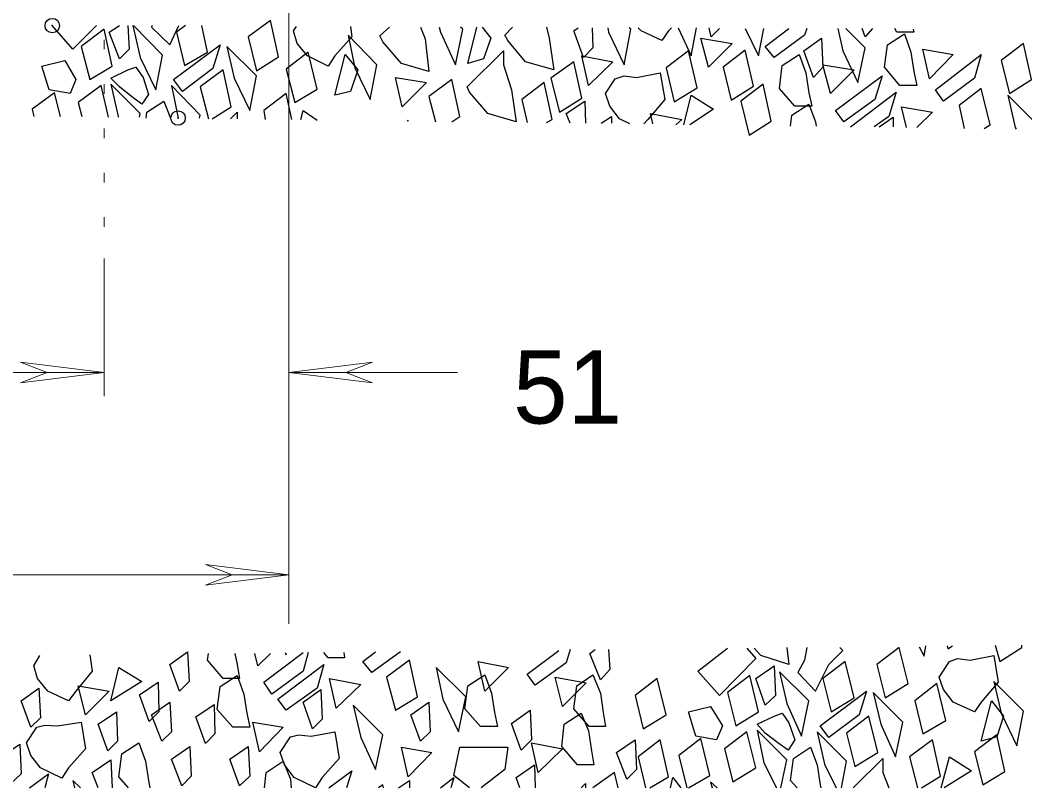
# Model space of a CAD drawing. Extents: x 312583 to 312854, y 144419 to 144597.
# Drawn here: x 312660.36 to 312670.78, y 144443.12 to 144451.08 of the extents above; entities that cross this region are included whole.
import ezdxf

# ---------------------------------------------------------------- set-up
doc = ezdxf.new("R2010")
doc.units = 0
doc.header["$LTSCALE"] = 0.3
doc.header["$PDMODE"] = 32
doc.header["$PDSIZE"] = 0.15
doc.linetypes.add('DOTTED', pattern=[1.5, 0.3, -1.2])
doc.layers.add('1', color=7, linetype='Continuous', lineweight=25)
doc.layers.add('2', color=7, linetype='Continuous', lineweight=13)

msp = doc.modelspace()

# ---------------------------------------------------------------- linework, layer by layer
at = {"layer": '1'}
for p, q in [((312661.8381, 144450.7184), (312661.5391, 144451.0251)), ((312661.9148, 144450.8258), (312662.0068, 144451.0251)), ((312662.3058, 144450.7491), (312662.2445, 144451.0251)), ((312664.9508, 144450.9868), (312664.9278, 144451.0098)), ((312665.1501, 144451.0098), (312665.2421, 144450.8948)), ((312666.6911, 144450.9868), (312666.6758, 144451.0021)), ((312667.1128, 144451.0021), (312667.0821, 144450.9714)), ((312668.5158, 144450.9944), (312668.4928, 144450.9254)), ((312669.1215, 144450.7951), (312668.9221, 144450.9944)), ((312661.8535, 144450.2431), (312661.9225, 144450.0668)), ((312666.2158, 144450.2431), (312666.2235, 144450.0131)), ((312661.6005, 144450.0744), (312661.6081, 144450.1128)), ((312662.3518, 144450.0591), (312662.5511, 144450.1818)), ((312667.5498, 144450.1588), (312667.3045, 144449.9978)), ((312669.8191, 144450.1281), (312669.6581, 144449.9671)), ((312662.2215, 144450.0668), (312662.2291, 144450.0974)), ((312664.8358, 144450.0284), (312664.9201, 144450.0821)), ((312665.8171, 144450.0208), (312665.8785, 144450.0514)), ((312666.3845, 144450.0131), (312666.4918, 144450.0821)), ((312666.4918, 144450.0821), (312666.4918, 144450.0131)), ((312666.8675, 144450.0514), (312666.8291, 144450.0054)), ((312667.2201, 144450.0514), (312667.1588, 144449.9978)), ((312669.3668, 144450.0821), (312669.2135, 144449.9748)), ((312669.2671, 144449.9748), (312669.4128, 144450.0744)), ((312669.4128, 144450.0744), (312669.4128, 144449.9748)), ((312670.3558, 144449.9594), (312670.4171, 144449.9978)), ((312670.7468, 144444.5774), (312670.7468, 144444.6004)), ((312663.3485, 144444.5238), (312663.2948, 144444.3321)), ((312666.0625, 144444.5544), (312666.0241, 144444.4164)), ((312661.3015, 144443.4121), (312661.3168, 144443.1208)), ((312665.6945, 144443.3584), (312665.7021, 144443.1208)), ((312668.2475, 144443.1208), (312668.3088, 144443.4121)), ((312668.8761, 144443.1208), (312668.9298, 144443.3968)), ((312665.3878, 144443.3124), (312665.1425, 144443.1208)), ((312667.2891, 144443.1208), (312667.5115, 144443.2511)), ((312669.3055, 144443.2818), (312669.3668, 144443.1208)), ((312669.7041, 144443.1208), (312669.9035, 144443.2434)), ((312670.2255, 144443.2971), (312669.9418, 144443.1208)), ((312664.2838, 144443.1208), (312664.3988, 144443.1974)), ((312664.3988, 144443.1974), (312664.3988, 144443.1208)), ((312666.8905, 144443.1208), (312667.0821, 144443.2358))]:
    msp.add_line(p, q, dxfattribs=at)
for points in [[(312663.0418, 144450.7031), (312662.9575, 144451.0788), (312662.7275, 144450.9101), (312662.8118, 144450.5574)], [(312661.3168, 144450.6034), (312661.2325, 144450.9868), (312660.9948, 144450.8104), (312661.0868, 144450.4654)], [(312664.0615, 144450.6188), (312663.7625, 144450.9254), (312663.8315, 144450.5881), (312663.9925, 144450.2584)], [(312667.7415, 144450.8411), (312667.4961, 144450.5958), (312667.4195, 144450.8948)], [(312668.6691, 144450.8948), (312668.6845, 144450.5958), (312668.5848, 144450.4884), (312668.4851, 144450.7644)], [(312669.5278, 144450.9408), (312669.5968, 144450.7491), (312669.6275, 144450.5498), (312669.6581, 144450.4041), (312669.4818, 144450.4041), (312669.3208, 144450.5958), (312669.3515, 144450.8258)], [(312670.8465, 144450.4654), (312670.7621, 144450.8411), (312670.5321, 144450.6648), (312670.6165, 144450.3198)], [(312662.3595, 144450.5804), (312662.0451, 144450.3428), (312661.9531, 144450.4654), (312662.4361, 144450.8258)], [(312662.8118, 144450.5038), (312662.5051, 144450.8104), (312662.5818, 144450.4808), (312662.7428, 144450.1434)], [(312663.4405, 144450.3658), (312663.3485, 144450.7491), (312663.1185, 144450.5728), (312663.2105, 144450.2278)], [(312665.3725, 144450.6188), (312665.4568, 144450.3581), (312665.5028, 144450.0284), (312665.2115, 144450.1128), (312665.0198, 144450.3351), (312664.9968, 144450.3888), (312665.3725, 144450.7644)], [(312667.3811, 144450.3811), (312667.2891, 144450.7644), (312667.0591, 144450.5881), (312667.1435, 144450.2354)], [(312667.9638, 144450.3964), (312667.8795, 144450.7721), (312667.6495, 144450.5958), (312667.7338, 144450.2508)], [(312670.0338, 144450.7261), (312669.7885, 144450.4731), (312669.7195, 144450.7798)], [(312660.8261, 144450.6648), (312660.9411, 144450.4654), (312660.8798, 144450.3198), (312660.6651, 144450.3581), (312660.5885, 144450.6034)], [(312663.8621, 144450.5651), (312663.7855, 144450.3428), (312663.6245, 144450.3044), (312663.7318, 144450.7261)], [(312666.1851, 144450.2738), (312666.1008, 144450.6494), (312665.8631, 144450.4808), (312665.9551, 144450.1281)], [(312666.5071, 144450.6494), (312666.2541, 144450.4041), (312666.1851, 144450.7108)], [(312668.4391, 144450.7261), (312668.5081, 144450.5344), (312668.5388, 144450.3274), (312668.5695, 144450.1894), (312668.3931, 144450.1894), (312668.2321, 144450.3734), (312668.2628, 144450.6111)], [(312670.2561, 144450.4808), (312669.9341, 144450.2431), (312669.8498, 144450.3581), (312670.3251, 144450.7261)], [(312661.4778, 144450.5651), (312661.5621, 144450.5958), (312661.6388, 144450.4884), (312661.6925, 144450.3121), (312661.6235, 144450.2124), (312661.5161, 144450.2891), (312661.3935, 144450.3888), (312661.3015, 144450.4808)], [(312669.0065, 144450.5651), (312668.7611, 144450.3198), (312668.6845, 144450.6188)], [(312664.5751, 144450.4348), (312664.3221, 144450.1818), (312664.2531, 144450.4884)], [(312669.2211, 144450.2584), (312668.8991, 144450.0284), (312668.8148, 144450.1434), (312669.2978, 144450.5038)], [(312668.1478, 144450.0361), (312668.0635, 144450.4194), (312667.8335, 144450.2431), (312667.9178, 144449.8904)], [(312662.0988, 144444.5314), (312662.1141, 144444.2248), (312662.0145, 144444.1251), (312661.9148, 144444.4011)], [(312669.5661, 144444.2018), (312669.4741, 144444.5774), (312669.2441, 144444.4011), (312669.3285, 144444.0561)], [(312670.3251, 144444.0101), (312670.2561, 144443.9104), (312670.0338, 144444.0101), (312669.9341, 144444.1404), (312669.8881, 144444.2708), (312669.9955, 144444.4318), (312670.0798, 144444.4624), (312670.2101, 144444.4471), (312670.4555, 144444.4931), (312670.5015, 144444.2171)], [(312663.4405, 144444.1558), (312663.1185, 144443.9258), (312663.0341, 144444.0408), (312663.5095, 144444.4011)], [(312664.4831, 144444.0638), (312664.3988, 144444.4471), (312664.1611, 144444.2708), (312664.2531, 144443.9258)], [(312665.4261, 144444.3704), (312665.1808, 144444.1251), (312665.1118, 144444.4318)], [(312668.1785, 144444.3858), (312668.1938, 144444.0791), (312668.0865, 144443.9794), (312667.9868, 144444.2554)], [(312669.0065, 144444.0561), (312668.9145, 144444.4318), (312668.6845, 144444.2554), (312668.7688, 144443.9104)], [(312661.6235, 144444.2248), (312661.3015, 144444.0254), (312661.3858, 144444.3704)], [(312662.6125, 144444.2861), (312662.6815, 144444.0944), (312662.7121, 144443.8951), (312662.7428, 144443.7494), (312662.5665, 144443.7494), (312662.4055, 144443.9334), (312662.4361, 144444.1711)], [(312664.9815, 144444.0638), (312664.6748, 144444.3704), (312664.7438, 144444.0408), (312664.9048, 144443.7034)], [(312665.1808, 144444.2938), (312665.2498, 144444.1021), (312665.2805, 144443.9028), (312665.3111, 144443.7571), (312665.1348, 144443.7571), (312664.9738, 144443.9411), (312665.0045, 144444.1788)], [(312666.3001, 144444.2938), (312666.3768, 144444.1021), (312666.4075, 144443.9028), (312666.4305, 144443.7571), (312666.2618, 144443.7571), (312666.1008, 144443.9411), (312666.1315, 144444.1788)], [(312668.0175, 144443.9104), (312667.9255, 144444.2861), (312667.6955, 144444.1098), (312667.7798, 144443.7648)], [(312668.5388, 144444.0254), (312668.2321, 144444.3244), (312668.3088, 144443.9948), (312668.4621, 144443.6574)], [(312661.2861, 144444.1251), (312661.0408, 144443.8798), (312660.9641, 144444.1788)], [(312661.7921, 144444.2171), (312661.7998, 144443.9104), (312661.7001, 144443.8108), (312661.6005, 144444.0868)], [(312663.8928, 144444.1941), (312663.6398, 144443.9488), (312663.5708, 144444.2554)], [(312666.2311, 144444.2094), (312665.9858, 144443.9641), (312665.9091, 144444.2708)], [(312667.0591, 144443.8798), (312666.9671, 144444.2554), (312666.7371, 144444.0791), (312666.8215, 144443.7341)], [(312669.9571, 144443.8184), (312669.8651, 144444.2018), (312669.6351, 144444.0254), (312669.7195, 144443.6804)], [(312670.7621, 144443.9181), (312670.4555, 144444.2248), (312670.5321, 144443.8951), (312670.6931, 144443.5578)], [(312660.5578, 144444.1558), (312660.5731, 144443.8491), (312660.4735, 144443.7494), (312660.3738, 144444.0254)], [(312663.4788, 144444.1404), (312663.4941, 144443.8338), (312663.3945, 144443.7341), (312663.2948, 144444.0101)], [(312669.0601, 144443.8798), (312668.7458, 144443.6421), (312668.6538, 144443.7648), (312669.1368, 144444.1251)], [(312669.5125, 144443.8031), (312669.2058, 144444.1098), (312669.2825, 144443.7801), (312669.4358, 144443.4428)], [(312661.9148, 144444.0101), (312661.9301, 144443.7034), (312661.8305, 144443.6038), (312661.7231, 144443.8798)], [(312662.3748, 144443.9871), (312662.3825, 144443.6804), (312662.2828, 144443.5808), (312662.1831, 144443.8568)], [(312664.1228, 144443.6728), (312663.8161, 144443.9794), (312663.8928, 144443.6421), (312664.0461, 144443.3124)], [(312664.5981, 144444.0101), (312664.6135, 144443.7034), (312664.5138, 144443.6038), (312664.4141, 144443.8798)], [(312670.5551, 144443.8644), (312670.4861, 144443.6498), (312670.3251, 144443.6038), (312670.4325, 144444.0254)], [(312661.3628, 144443.9104), (312661.3705, 144443.6038), (312661.2708, 144443.5041), (312661.1711, 144443.7801)], [(312665.6485, 144443.9258), (312665.6638, 144443.6191), (312665.5565, 144443.5118), (312665.4568, 144443.7878)], [(312666.1775, 144443.8951), (312666.2541, 144443.7111), (312666.2848, 144443.5041), (312666.3078, 144443.3584), (312666.1391, 144443.3584), (312665.9781, 144443.5501), (312666.0011, 144443.7801)], [(312667.5191, 144443.9641), (312667.6418, 144443.7648), (312667.5805, 144443.6191), (312667.3658, 144443.6574), (312667.2891, 144443.9104)], [(312668.1785, 144443.8644), (312668.2628, 144443.8951), (312668.3318, 144443.7954), (312668.3931, 144443.6191), (312668.3241, 144443.5118), (312668.2168, 144443.5884), (312668.0865, 144443.6881), (312668.0021, 144443.7801)], [(312669.2518, 144443.4888), (312669.1598, 144443.8644), (312668.9298, 144443.6881), (312669.0141, 144443.3431)], [(312660.8645, 144443.3278), (312660.7955, 144443.2204), (312660.5731, 144443.3278), (312660.4735, 144443.4581), (312660.4275, 144443.5884), (312660.5348, 144443.7494), (312660.6191, 144443.7724), (312660.7495, 144443.7648), (312660.9948, 144443.8031), (312661.0408, 144443.5271)], [(312663.0878, 144443.7494), (312662.8425, 144443.4964), (312662.7735, 144443.8031)], [(312663.4941, 144443.2281), (312663.4251, 144443.1208), (312663.2028, 144443.2281), (312663.1031, 144443.3584), (312663.0571, 144443.4888), (312663.1645, 144443.6498), (312663.2488, 144443.6728), (312663.3791, 144443.6574), (312663.6245, 144443.7034), (312663.6705, 144443.4274)], [(312667.9868, 144443.3278), (312667.8948, 144443.7034), (312667.6648, 144443.5271), (312667.7491, 144443.1821)], [(312670.5705, 144443.2894), (312670.4861, 144443.6728), (312670.2561, 144443.4964), (312670.3405, 144443.1514)], [(312660.3585, 144443.5731), (312660.3738, 144443.2664), (312660.2665, 144443.1668), (312660.1668, 144443.4428)], [(312662.1218, 144443.5501), (312662.1371, 144443.2434), (312662.0375, 144443.1438), (312661.9301, 144443.4198)], [(312662.7275, 144443.5501), (312662.7428, 144443.2434), (312662.6355, 144443.1438), (312662.5358, 144443.4198)], [(312665.9858, 144443.5271), (312665.7328, 144443.2818), (312665.6638, 144443.5884)], [(312666.7371, 144443.6191), (312666.7525, 144443.3124), (312666.6528, 144443.2128), (312666.5455, 144443.4888)], [(312664.6288, 144443.4888), (312664.3835, 144443.2358), (312664.3145, 144443.5424)]]:
    msp.add_lwpolyline(points, close=True, dxfattribs=at)
for points in [[(312661.1558, 144451.0251), (312660.9105, 144450.7798), (312660.6958, 144451.0251)], [(312661.4778, 144451.0251), (312661.4931, 144450.7798), (312661.3935, 144450.6801), (312661.2861, 144450.9561), (312661.3935, 144451.0251)], [(312661.5315, 144451.0251), (312661.6081, 144450.6954), (312661.7691, 144450.3581), (312661.8381, 144450.7184)], [(312661.7308, 144451.0251), (312661.7231, 144451.0098), (312661.9148, 144450.8258)], [(312662.0758, 144451.0251), (312661.9838, 144450.9561), (312662.0681, 144450.6111), (312662.3058, 144450.7491)], [(312663.6245, 144450.7108), (312663.5555, 144450.6034), (312663.3408, 144450.7108), (312663.2335, 144450.8411), (312663.1951, 144450.9714), (312663.2258, 144451.0174)], [(312663.7855, 144451.0174), (312663.8008, 144450.9101), (312663.6245, 144450.7108)], [(312664.5138, 144451.0098), (312664.5598, 144450.8871), (312664.5981, 144450.5498), (312664.3145, 144450.6341), (312664.1228, 144450.8564), (312664.0921, 144450.9178), (312664.1918, 144451.0098)], [(312664.7055, 144451.0098), (312664.7208, 144450.9561), (312664.8741, 144450.6188), (312664.9508, 144450.9868)], [(312665.2421, 144450.8948), (312665.1655, 144450.6801), (312665.0045, 144450.6341), (312665.0965, 144451.0098)], [(312665.8171, 144451.0098), (312665.8478, 144450.8948), (312665.8938, 144450.5651), (312665.6025, 144450.6494), (312665.4185, 144450.8718), (312665.3878, 144450.9254), (312665.4645, 144451.0098)], [(312666.2925, 144451.0021), (312666.3001, 144450.7951), (312666.2005, 144450.6954), (312666.1008, 144450.9714), (312666.1468, 144451.0021)], [(312666.4535, 144451.0021), (312666.4611, 144450.9561), (312666.6221, 144450.6188), (312666.6911, 144450.9868)], [(312667.0821, 144450.9714), (312667.0131, 144450.8718), (312666.7985, 144450.9714), (312666.7678, 144451.0021)], [(312667.1818, 144451.0021), (312667.3198, 144450.7108), (312667.3735, 144451.0021)], [(312667.6111, 144450.9944), (312667.5268, 144450.9101), (312667.5038, 144451.0021)], [(312667.8795, 144450.9944), (312668.0175, 144450.7108), (312668.0711, 144450.9944)], [(312668.4928, 144450.9254), (312668.1785, 144450.6954), (312668.0865, 144450.8104), (312668.3318, 144450.9944)], [(312668.8378, 144450.9944), (312668.8915, 144450.7644), (312669.0448, 144450.4348), (312669.1215, 144450.7951)], [(312669.1981, 144450.9944), (312669.1215, 144450.9101), (312669.0908, 144450.9944)], [(312669.6198, 144450.9868), (312669.6275, 144450.9561), (312669.4511, 144450.9561), (312669.4281, 144450.9944)], [(312662.5511, 144450.1818), (312662.4668, 144450.5651), (312662.2291, 144450.3888), (312662.3135, 144450.0591)], [(312666.6835, 144450.0054), (312666.5761, 144450.0591), (312666.4765, 144450.1894), (312666.4305, 144450.3198), (312666.5301, 144450.4731), (312666.6221, 144450.5038), (312666.7525, 144450.4884), (312666.9978, 144450.5344), (312667.0438, 144450.2584), (312666.8675, 144450.0514)], [(312664.9201, 144450.0821), (312664.8358, 144450.4654), (312664.5981, 144450.2891), (312664.6671, 144450.0284)], [(312665.8785, 144450.0514), (312665.7941, 144450.4348), (312665.5641, 144450.2584), (312665.6178, 144450.0208)], [(312660.7801, 144450.0821), (312660.7188, 144450.3274), (312660.4888, 144450.1588), (312660.5041, 144450.0821)], [(312661.2785, 144450.0744), (312661.2018, 144450.4041), (312660.9641, 144450.2278), (312661.0025, 144450.0821)], [(312661.6081, 144450.1128), (312661.3015, 144450.4194), (312661.3781, 144450.0821), (312661.3781, 144450.0744)], [(312662.2291, 144450.0974), (312661.9301, 144450.4041), (312661.9991, 144450.0668)], [(312663.1798, 144450.0514), (312663.1185, 144450.3198), (312662.8885, 144450.1434), (312662.9038, 144450.0514)], [(312668.9681, 144449.9748), (312669.4435, 144450.3351), (312669.3668, 144450.0821)], [(312670.4171, 144449.9978), (312670.3251, 144450.3734), (312670.0951, 144450.1971), (312670.1488, 144449.9594)], [(312661.6695, 144450.0668), (312661.6771, 144450.1281), (312661.8535, 144450.2431)], [(312666.0625, 144450.0131), (312666.0241, 144450.1128), (312666.2158, 144450.2431)], [(312667.2431, 144449.9978), (312667.3198, 144450.3044), (312667.5498, 144450.1588)], [(312670.9078, 144449.9978), (312670.6011, 144450.3044), (312670.6778, 144449.9671), (312670.6855, 144449.9518)], [(312662.5435, 144450.0591), (312662.6125, 144450.1281), (312662.6125, 144450.0591)], [(312663.2718, 144450.0514), (312663.2948, 144450.1434), (312663.4405, 144450.0438)], [(312666.9211, 144450.0054), (312666.8981, 144450.1128), (312667.2201, 144450.0514)], [(312668.3471, 144449.9824), (312668.3625, 144450.0974), (312668.5388, 144450.2124)], [(312668.5388, 144450.2124), (312668.6078, 144450.0284), (312668.6155, 144449.9824)], [(312669.5508, 144449.9671), (312669.4971, 144450.1818), (312669.8191, 144450.1281)], [(312664.3835, 144450.0361), (312664.3835, 144450.0438), (312664.3758, 144450.0361)], [(312669.6811, 144444.5851), (312669.7348, 144444.4854), (312669.7501, 144444.5928)], [(312669.9725, 144444.5928), (312669.9801, 144444.5621), (312670.0261, 144444.5928)], [(312670.4708, 144444.6004), (312670.5168, 144444.4318), (312670.7468, 144444.5774)], [(312660.9411, 144444.1251), (312660.8645, 144444.0254), (312660.6498, 144444.1251), (312660.5425, 144444.2554), (312660.5041, 144444.3858), (312660.5655, 144444.4931)], [(312661.0868, 144444.5008), (312661.1098, 144444.3321), (312660.9411, 144444.1251)], [(312662.5895, 144444.5161), (312662.6125, 144444.4011), (312662.6355, 144444.2554), (312662.4668, 144444.2554), (312662.3058, 144444.4471), (312662.3135, 144444.5161)], [(312662.9575, 144444.5161), (312662.8271, 144444.3858), (312662.7965, 144444.5161)], [(312663.2948, 144444.3321), (312662.9728, 144444.0944), (312662.8885, 144444.2171), (312663.2948, 144444.5238)], [(312663.1108, 144444.5238), (312663.1185, 144444.5008), (312663.1185, 144444.5161)], [(312663.7165, 144444.5238), (312663.7241, 144444.4701), (312663.5555, 144444.4701), (312663.5095, 144444.5238)], [(312664.3068, 144444.5314), (312664.0078, 144444.3168), (312663.9158, 144444.4318), (312664.0461, 144444.5314)], [(312666.0241, 144444.4164), (312665.7021, 144444.1864), (312665.6178, 144444.3014), (312665.9475, 144444.5468)], [(312666.4611, 144444.5544), (312666.4765, 144444.3474), (312666.3768, 144444.2401), (312666.2695, 144444.5161), (312666.3231, 144444.5544)], [(312667.8948, 144444.5698), (312667.9868, 144444.4624), (312667.6111, 144444.0791), (312667.3888, 144444.3321), (312667.6955, 144444.5698)], [(312668.3088, 144444.5774), (312668.3318, 144444.4011), (312668.0405, 144444.4931), (312667.9715, 144444.5698)], [(312668.5158, 144444.5774), (312668.4928, 144444.4471), (312668.4238, 144444.3168), (312668.6078, 144444.1251)], [(312668.6078, 144444.1251), (312668.7458, 144444.4011), (312668.8915, 144444.5468), (312668.8608, 144444.5774)], [(312668.3088, 144443.4121), (312668.0021, 144443.7188), (312668.0711, 144443.3814), (312668.2015, 144443.1208)], [(312668.9298, 144443.3968), (312668.6231, 144443.7034), (312668.6998, 144443.3661), (312668.8225, 144443.1208)], [(312661.4855, 144443.1208), (312661.3858, 144443.2358), (312661.4165, 144443.4734), (312661.5928, 144443.5884)], [(312661.5928, 144443.5884), (312661.6618, 144443.3968), (312661.6925, 144443.1974), (312661.7078, 144443.1208)], [(312667.0821, 144443.2358), (312666.9978, 144443.6191), (312666.7678, 144443.4428), (312666.8445, 144443.1208)], [(312667.5115, 144443.2511), (312667.4195, 144443.6344), (312667.1895, 144443.4581), (312667.2738, 144443.1208)], [(312669.9035, 144443.2434), (312669.8191, 144443.6191), (312669.5815, 144443.4428), (312669.6658, 144443.1208)], [(312665.0198, 144443.1208), (312664.8588, 144443.2511), (312664.9201, 144443.5424), (312665.4185, 144443.5424), (312665.3878, 144443.3124)], [(312668.4161, 144443.1208), (312668.3471, 144443.1974), (312668.3778, 144443.4274), (312668.5541, 144443.5424)], [(312668.5541, 144443.5424), (312668.6231, 144443.3584), (312668.6538, 144443.1514), (312668.6615, 144443.1208)], [(312661.1711, 144443.1208), (312661.1098, 144443.2818), (312661.3015, 144443.4121)], [(312662.8961, 144443.1208), (312662.9115, 144443.2818), (312663.0878, 144443.3968)], [(312663.0878, 144443.3968), (312663.1645, 144443.2128), (312663.1721, 144443.1208)], [(312665.5411, 144443.1208), (312665.5028, 144443.2281), (312665.6945, 144443.3584)], [(312668.9988, 144443.1208), (312669.3055, 144443.4274), (312669.3055, 144443.2818)], [(312669.9111, 144443.1208), (312669.9955, 144443.4428), (312670.2255, 144443.2971)], [(312660.4581, 144443.1208), (312660.6575, 144443.2664), (312660.6191, 144443.1208)], [(312663.5631, 144443.1208), (312663.8008, 144443.2971), (312663.7471, 144443.1208)], [(312666.5608, 144443.1208), (312666.5225, 144443.2818), (312666.3001, 144443.1208)], [(312660.9871, 144443.1208), (312660.9105, 144443.1974), (312660.9258, 144443.1208)], [(312664.1305, 144443.1208), (312664.1228, 144443.1514), (312664.0768, 144443.1208)], [(312664.7208, 144443.1208), (312664.8588, 144443.2281), (312664.8281, 144443.1208)], [(312666.1775, 144443.1208), (312666.2235, 144443.1668), (312666.2235, 144443.1208)], [(312667.1051, 144443.1208), (312667.1281, 144443.2281), (312667.2125, 144443.1208)], [(312667.5881, 144443.1208), (312667.5191, 144443.1821), (312667.5345, 144443.1208)]]:
    msp.add_lwpolyline(points, dxfattribs=at)
for p in [(312660.6958, 144451.0251), (312661.9991, 144450.0668)]:
    msp.add_point(p, dxfattribs=at)
at = {"layer": '2'}
for p, q in [((312663.1491, 144454.5058), (312663.1491, 144444.8228)), ((312661.2325, 144448.6101), (312661.2325, 144447.1841)), ((312660.3661, 144447.5368), (312660.6421, 144447.4294)), ((312661.2325, 144447.4294), (312660.3661, 144447.5368)), ((312663.1491, 144447.4294), (312664.0155, 144447.5368)), ((312664.0155, 144447.5368), (312663.7395, 144447.4294)), ((312659.8218, 144447.4294), (312661.2325, 144447.4294)), ((312660.3661, 144447.3221), (312660.6421, 144447.4294)), ((312661.2325, 144447.4294), (312660.3661, 144447.3221)), ((312663.1491, 144447.4294), (312664.8971, 144447.4294)), ((312663.1491, 144447.4294), (312664.0155, 144447.3221)), ((312664.0155, 144447.3221), (312663.7395, 144447.4294)), ((312662.2828, 144445.4361), (312662.5588, 144445.3288)), ((312663.1491, 144445.3288), (312662.2828, 144445.4361)), ((312647.3405, 144445.3288), (312663.1491, 144445.3288)), ((312662.2828, 144445.2214), (312662.5588, 144445.3288)), ((312663.1491, 144445.3288), (312662.2828, 144445.2214))]:
    msp.add_line(p, q, dxfattribs=at)
at = {"layer": '2', "linetype": 'DOTTED'}
msp.add_line((312661.2325, 144454.0994), (312661.2325, 144448.8248), dxfattribs=at)

# ---------------------------------------------------------------- texts
at = {"layer": '2'}
msp.add_text('51 ', height=0.76, dxfattribs=at).set_placement((312665.4721, 144446.8994))

doc.saveas('drawing.dxf')
